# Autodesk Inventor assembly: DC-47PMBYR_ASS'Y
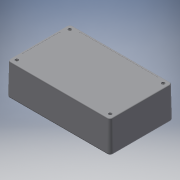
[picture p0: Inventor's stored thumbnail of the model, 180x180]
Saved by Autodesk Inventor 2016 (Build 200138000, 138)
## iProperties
Created: 2010-08
Part Number: DC-47PMBYR_ASS'Y
Description: STEP AP214
Document SubType Name: Assembly
Designer: irish_000
Title: DC-47PMBYR_ASS'Y.STEP
Revision Number: ANY
Sending System: SolidWorks 2010
Preprocessor: SwSTEP 2.0
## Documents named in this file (4)
- C:\Users\irish_000\Downloads\14531129045667030\DC-47PMBYR_ASS'Y.iam
- C:\Users\irish_000\Downloads\14531129045667030\SCREWS-DC-BR.ipt
- C:\Users\irish_000\Downloads\14531129045667030\DC-47C_DC-47C-R.ipt
- C:\Users\irish_000\Downloads\14531129045667030\DC-47B_DC-47BPMBY.ipt
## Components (6 placed, 6 different names)
1. SCREWS-DC-BR_1
2. SCREWS-DC-BR_2
3. SCREWS-DC-BR_3
4. SCREWS-DC-BR_4
5. DC-47C_DC-47C-R_5
6. DC-47B_DC-47BPMBY_6
